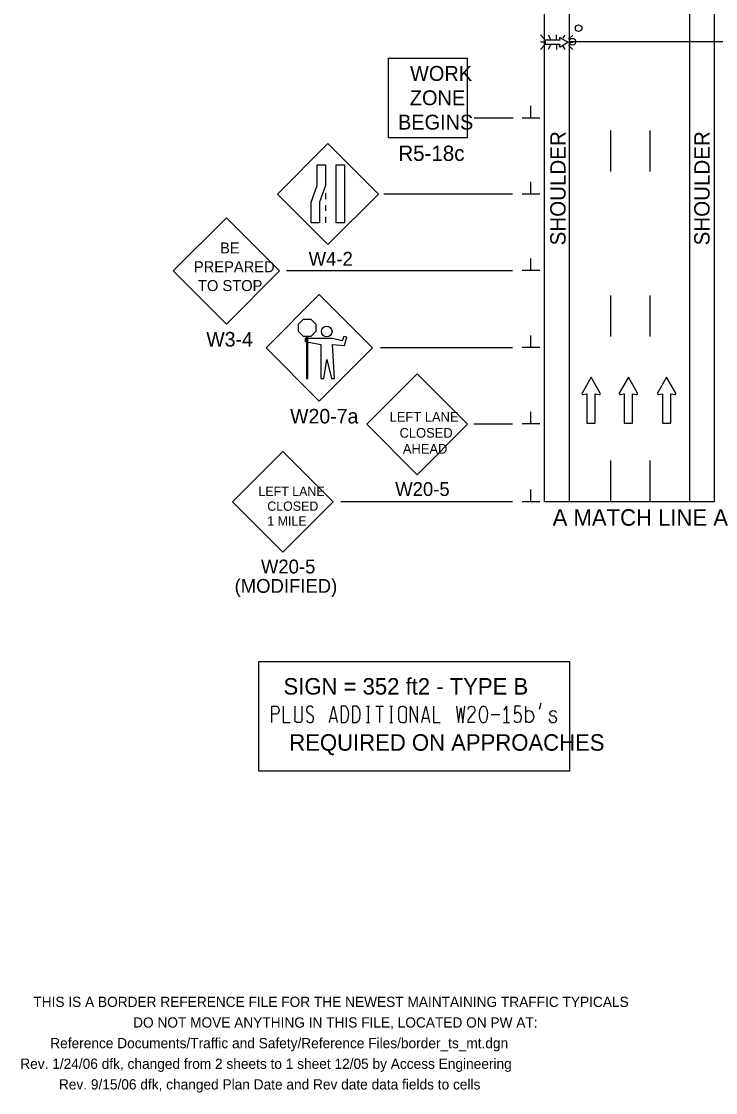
# Model space of a CAD drawing. Extents: x -1809 to 1557, y -1087 to 44.
# Drawn here: x -1809 to -1388, y -1087 to -438 of the extents above; entities that cross this region are included whole.
import ezdxf

# ---------------------------------------------------------------- set-up
doc = ezdxf.new("R2010")
doc.units = 0
for name, color, linetype in [('BORDER', 7, 'Continuous'), ('MT_SCRATCH_LEVEL_A', 7, 'Continuous'), ('MT_SCRATCH_LEVEL_E', 7, 'Continuous'), ('MT_STAGE_1A_NOTES', 7, 'Continuous'), ('PAVT_EDGE_EX', 7, 'Continuous'), ('SCRATCH_LEVEL_A', 7, 'Continuous'), ('SCRATCH_LEVEL_C', 7, 'Continuous'), ('TRAFFIC_SIGNS_PR', 7, 'Continuous'), ('TYPICAL_EX', 7, 'Continuous'), ('TYPICAL_TEXT_DIMEN_EX', 7, 'Continuous')]:
    doc.layers.add(name, color=color, linetype=linetype)

msp = doc.modelspace()

# ---------------------------------------------------------------- linework, layer by layer
at = {"layer": 'BORDER'}
for p, q in [((-1403.94, -403.77), (-1403.94, -728.63)), ((-1451.94, -503.63), (-1451.94, -528.63)), ((-1427.94, -503.63), (-1427.94, -528.63)), ((-1451.94, -603.63), (-1451.94, -628.63)), ((-1427.94, -603.63), (-1427.94, -628.63)), ((-1451.94, -703.63), (-1451.94, -728.63)), ((-1427.94, -703.63), (-1427.94, -728.63))]:
    msp.add_line(p, q, dxfattribs=at)
at = {"layer": 'MT_SCRATCH_LEVEL_A'}
msp.add_line((-1476.89, -407), (-1476.89, -728.63), dxfattribs=at)
at = {"layer": 'MT_SCRATCH_LEVEL_E'}
for p, q in [((-1463.64, -653.15), (-1469.12, -662.8)), ((-1458.11, -662.8), (-1463.64, -653.15)), ((-1441.03, -653.15), (-1446.51, -662.8)), ((-1435.5, -662.8), (-1441.03, -653.15)), ((-1417.86, -653.15), (-1423.34, -662.8)), ((-1412.33, -662.8), (-1417.86, -653.15)), ((-1468.47, -663.71), (-1466.1, -663.29)), ((-1466.1, -663.29), (-1466.1, -680.97)), ((-1461.12, -680.97), (-1461.12, -663.29)), ((-1461.12, -663.29), (-1458.75, -663.71)), ((-1445.87, -663.71), (-1443.5, -663.29)), ((-1443.5, -663.29), (-1443.5, -680.97)), ((-1438.51, -680.97), (-1438.51, -663.29)), ((-1438.51, -663.29), (-1436.14, -663.71)), ((-1422.69, -663.71), (-1420.32, -663.29)), ((-1420.32, -663.29), (-1420.32, -680.97)), ((-1415.34, -680.97), (-1415.34, -663.29)), ((-1415.34, -663.29), (-1412.97, -663.71)), ((-1466.1, -680.97), (-1461.12, -680.97)), ((-1443.5, -680.97), (-1438.51, -680.97)), ((-1420.32, -680.97), (-1415.34, -680.97))]:
    msp.add_line(p, q, dxfattribs=at)
for centre, start, end in [((-1468.57, -663.1), 150.42484, 279.96381), ((-1458.65, -663.1), 260.03619, 29.77312), ((-1445.97, -663.1), 150.42484, 279.96381), ((-1436.05, -663.1), 260.03619, 29.77312), ((-1422.79, -663.1), 150.42484, 279.96381), ((-1412.87, -663.1), 260.03619, 29.77312)]:
    msp.add_arc(centre, 0.617, start, end, dxfattribs=at)
at = {"layer": 'MT_STAGE_1A_NOTES'}
for p, q in [((-1270.82, -449.93), (-1476.89, -449.93)), ((-1510.9, -496.19), (-1534.4, -496.19)), ((-1511.17, -542.25), (-1589.17, -542.25)), ((-1511.17, -588.81), (-1648.17, -588.81)), ((-1511.17, -635.38), (-1591.17, -635.39)), ((-1511.17, -681.74), (-1534.67, -681.74)), ((-1511.17, -728.63), (-1615.18, -728.63))]:
    msp.add_line(p, q, dxfattribs=at)
at = {"layer": 'PAVT_EDGE_EX'}
for p, q in [((-1492.05, -380.59), (-1492.05, -728.63)), ((-1389.15, -407), (-1389.15, -728.63)), ((-1389.15, -728.63), (-1491.84, -728.63))]:
    msp.add_line(p, q, dxfattribs=at)
at = {"layer": 'SCRATCH_LEVEL_C'}
for p, q in [((-1664.91, -825.36), (-1476.63, -825.36)), ((-1664.91, -891.86), (-1664.91, -825.36)), ((-1476.63, -825.36), (-1476.63, -891.86)), ((-1632.6, -852.88), (-1632.02, -853.27)), ((-1476.63, -891.86), (-1664.91, -891.86))]:
    msp.add_line(p, q, dxfattribs=at)
for points in [[(-1657.1, -862.49), (-1657.1, -852.49)], [(-1657.1, -852.49), (-1654.19, -852.49)], [(-1654.19, -852.49), (-1653.31, -852.91), (-1652.69, -854.52), (-1652.69, -855.41), (-1653.31, -857.07), (-1654.19, -857.44)], [(-1650.1, -852.49), (-1650.1, -862.49)], [(-1643.1, -852.49), (-1643.1, -860.41)], [(-1638.73, -860.41), (-1638.73, -852.49)], [(-1635.56, -853.27), (-1636.09, -854.52), (-1636.09, -854.94), (-1635.54, -856.19)], [(-1632.6, -852.88), (-1633.17, -852.49), (-1634.35, -852.49), (-1635.56, -853.27)], [(-1635.54, -856.19), (-1632.29, -858.32)], [(-1622.1, -862.49), (-1619.77, -852.49)], [(-1619.77, -852.49), (-1617.44, -862.49)], [(-1612.48, -852.49), (-1615.1, -852.49)], [(-1615.1, -852.49), (-1615.1, -862.49)], [(-1612.48, -852.49), (-1611.57, -853.27), (-1610.97, -854.94), (-1610.65, -857.15), (-1611, -859.91), (-1611.6, -861.68), (-1612.48, -862.49)], [(-1605.48, -852.49), (-1608.1, -852.49)], [(-1608.1, -852.49), (-1608.1, -862.49)], [(-1605.48, -852.49), (-1604.57, -853.27), (-1603.97, -854.94), (-1603.65, -857.15), (-1604, -859.91), (-1604.6, -861.68), (-1605.48, -862.49)], [(-1599.65, -852.49), (-1597.9, -852.49)], [(-1598.77, -852.49), (-1598.77, -862.49)], [(-1594.1, -852.49), (-1589.44, -852.49)], [(-1591.77, -852.49), (-1591.77, -862.49)], [(-1585.65, -852.49), (-1583.9, -852.49)], [(-1584.77, -852.49), (-1584.77, -862.49)], [(-1580.07, -854.37), (-1579.92, -853.69), (-1579.56, -853.19), (-1578.84, -852.71), (-1578.15, -852.49), (-1577.22, -852.49), (-1576.76, -852.67), (-1575.87, -853.24), (-1575.56, -853.69), (-1575.41, -854.37)], [(-1580.07, -860.62), (-1580.07, -854.37)], [(-1575.41, -860.62), (-1575.41, -854.37)], [(-1573.1, -862.49), (-1573.1, -852.49)], [(-1573.1, -852.49), (-1568.69, -862.49)], [(-1568.69, -862.49), (-1568.69, -852.49)], [(-1566.1, -862.49), (-1563.77, -852.49)], [(-1563.77, -852.49), (-1561.44, -862.49)], [(-1559.1, -852.49), (-1559.1, -862.49)], [(-1545.1, -852.49), (-1543.94, -862.49)], [(-1543.94, -862.49), (-1542.61, -853.49)], [(-1542.61, -853.49), (-1541.31, -862.52)], [(-1541.31, -862.52), (-1540.09, -852.49)], [(-1538.1, -854.57), (-1537.83, -853.64), (-1537.23, -852.88), (-1536.35, -852.49), (-1535.77, -852.49), (-1534.9, -852.88)], [(-1535.66, -857.75), (-1534.29, -856.19)], [(-1534.9, -852.88), (-1534.3, -853.67), (-1534.02, -854.55), (-1534.02, -855.41), (-1534.29, -856.19)], [(-1530.88, -860.5), (-1531.13, -858.39), (-1531.13, -856.7), (-1530.88, -854.58)], [(-1530.88, -854.58), (-1530, -852.95), (-1529.11, -852.55), (-1528.51, -852.55), (-1527.61, -852.97), (-1526.74, -854.61)], [(-1526.74, -854.61), (-1526.46, -856.72), (-1526.48, -858.39), (-1526.74, -860.5)], [(-1514.77, -852.49), (-1516.52, -854.99)], [(-1514.77, -852.49), (-1514.77, -862.49)], [(-1509.81, -852.49), (-1510.1, -857.07)], [(-1510.1, -857.07), (-1508.68, -856.19), (-1507.76, -856.14), (-1506.9, -856.66), (-1506.29, -857.49), (-1506.02, -858.74), (-1506.02, -859.39)], [(-1506.31, -852.49), (-1509.81, -852.49)], [(-1503.07, -862.49), (-1503.07, -852.49)], [(-1503.07, -856.03), (-1502.16, -855.3)], [(-1502.16, -855.3), (-1501.28, -855.15)], [(-1501.28, -855.15), (-1500.52, -855.3)], [(-1500.52, -855.3), (-1499.79, -855.82)], [(-1499.79, -855.82), (-1499.31, -856.24)], [(-1499.31, -856.24), (-1498.88, -856.92)], [(-1494.92, -854.38), (-1493.77, -850.41)], [(-1488.59, -856.81), (-1488.49, -856.24)], [(-1488.49, -856.24), (-1488.12, -855.72)], [(-1488.12, -855.72), (-1487.43, -855.25)], [(-1487.43, -855.25), (-1486.7, -855.15)], [(-1486.7, -855.15), (-1486.08, -855.25)], [(-1486.08, -855.25), (-1485.5, -855.41)], [(-1485.5, -855.41), (-1484.99, -855.88)], [(-1484.99, -855.88), (-1484.58, -856.29)], [(-1654.19, -857.44), (-1657.1, -857.44)], [(-1650.1, -862.49), (-1646.02, -862.49)], [(-1638.73, -860.41), (-1639.02, -861.87), (-1639.6, -862.49), (-1641.94, -862.49), (-1642.83, -861.71), (-1643.1, -860.41)], [(-1636.1, -861.24), (-1635.21, -862.13)], [(-1635.21, -862.13), (-1634.48, -862.45), (-1633.19, -862.44), (-1632.29, -861.71)], [(-1632.29, -861.71), (-1631.7, -860.43), (-1631.71, -859.57), (-1632.29, -858.32)], [(-1618.02, -859.99), (-1621.52, -859.99)], [(-1615.1, -862.49), (-1612.48, -862.49)], [(-1608.1, -862.49), (-1605.48, -862.49)], [(-1599.65, -862.49), (-1597.9, -862.49)], [(-1585.65, -862.49), (-1583.9, -862.49)], [(-1580.07, -860.62), (-1579.92, -861.29), (-1579.56, -861.79), (-1578.84, -862.27), (-1578.15, -862.49), (-1577.22, -862.49), (-1576.76, -862.32), (-1575.87, -861.74), (-1575.56, -861.29), (-1575.41, -860.62)], [(-1562.02, -859.99), (-1565.52, -859.99)], [(-1559.1, -862.49), (-1555.02, -862.49)], [(-1538.1, -861.66), (-1537.83, -860.85)], [(-1538.1, -862.49), (-1538.1, -861.66)], [(-1534.02, -862.49), (-1538.1, -862.49)], [(-1537.83, -860.85), (-1535.66, -857.75)], [(-1526.74, -860.5), (-1527.65, -862.14), (-1528.52, -862.55), (-1529.13, -862.55), (-1530, -862.16), (-1530.88, -860.5)], [(-1524.1, -857.49), (-1518.85, -857.49)], [(-1516.62, -862.49), (-1512.99, -862.49)], [(-1506.02, -859.39), (-1506, -859.99), (-1506.29, -861.24), (-1506.9, -862.1), (-1508.08, -862.49), (-1508.94, -862.4), (-1509.56, -862.1), (-1510.1, -861.27)], [(-1502.38, -862.28), (-1503.07, -861.66)], [(-1501.28, -862.49), (-1502.38, -862.28)], [(-1500.44, -862.33), (-1501.28, -862.49)], [(-1499.86, -861.92), (-1500.44, -862.33)], [(-1499.06, -861.03), (-1499.86, -861.92)], [(-1498.77, -860.51), (-1499.06, -861.03)], [(-1498.88, -856.92), (-1498.62, -857.54)], [(-1498.44, -859.68), (-1498.77, -860.51)], [(-1498.62, -857.54), (-1498.44, -858.12)], [(-1498.44, -858.12), (-1498.4, -858.84)], [(-1498.4, -858.84), (-1498.44, -859.68)], [(-1488.92, -860.15), (-1489.03, -860.51)], [(-1489.03, -860.51), (-1488.92, -861.08)], [(-1488.92, -861.08), (-1488.67, -861.66)], [(-1488.67, -861.66), (-1487.61, -862.44)], [(-1488.41, -857.44), (-1488.59, -856.81)], [(-1488.16, -857.91), (-1488.41, -857.44)], [(-1487.72, -858.27), (-1488.16, -857.91)], [(-1487.14, -858.43), (-1487.72, -858.27)], [(-1487.61, -862.44), (-1486.74, -862.49)], [(-1486.66, -858.48), (-1487.14, -858.43)], [(-1486.74, -862.49), (-1485.97, -862.44)], [(-1485.9, -858.64), (-1486.66, -858.48)], [(-1485.97, -862.44), (-1485.46, -862.18)], [(-1485.31, -858.9), (-1485.9, -858.64)], [(-1485.46, -862.18), (-1485.02, -861.87)], [(-1484.88, -859.31), (-1485.31, -858.9)], [(-1485.02, -861.87), (-1484.58, -861.24)], [(-1484.58, -859.89), (-1484.88, -859.31)], [(-1484.44, -860.46), (-1484.58, -859.89)], [(-1484.58, -861.24), (-1484.44, -860.46)]]:
    msp.add_lwpolyline(points, dxfattribs=at)
at = {"layer": 'TRAFFIC_SIGNS_PR'}
for p, q in [((-1491.77, -448.4), (-1494.31, -445.86)), ((-1489.7, -445.87), (-1488.24, -448.41)), ((-1484.5, -448.41), (-1484.49, -445.87)), ((-1479.57, -445.88), (-1480.66, -447.76)), ((-1474.68, -445.89), (-1477.22, -448.42)), ((-1491.78, -452.06), (-1494.32, -454.6)), ((-1491.77, -450.23), (-1494.31, -450.23)), ((-1488.22, -452.07), (-1489.69, -454.6)), ((-1484.5, -452.07), (-1484.5, -454.61)), ((-1480.74, -452.64), (-1479.6, -454.61)), ((-1477.22, -450.25), (-1474.68, -450.25)), ((-1474.69, -454.62), (-1477.22, -452.08)), ((-1586.43, -507.87), (-1586.43, -459.87)), ((-1586.43, -459.87), (-1538.43, -459.87)), ((-1538.43, -507.87), (-1538.43, -459.87)), ((-1623.04, -511.7), (-1653.58, -542.25)), ((-1592.49, -542.25), (-1623.04, -511.7)), ((-1586.43, -507.87), (-1538.43, -507.87)), ((-1653.58, -542.25), (-1623.04, -572.8)), ((-1624.44, -541.7), (-1624.44, -545.3)), ((-1623.04, -572.8), (-1592.49, -542.25)), ((-1624.44, -548.9), (-1624.44, -552.5)), ((-1684.56, -556.57), (-1716.8, -588.81)), ((-1652.32, -588.81), (-1684.56, -556.57)), ((-1624.44, -556.1), (-1624.44, -559.7)), ((-1716.8, -588.81), (-1684.56, -621.05)), ((-1684.56, -621.05), (-1652.32, -588.81)), ((-1628.31, -603.15), (-1660.56, -635.39)), ((-1596.07, -635.39), (-1628.31, -603.15)), ((-1660.56, -635.39), (-1628.31, -667.63)), ((-1628.31, -667.63), (-1596.07, -635.39)), ((-1568.97, -651.19), (-1599.52, -681.74)), ((-1538.43, -681.74), (-1568.97, -651.19)), ((-1599.52, -681.74), (-1568.97, -712.29)), ((-1568.97, -712.29), (-1538.43, -681.74)), ((-1650.33, -698.13), (-1680.88, -728.67)), ((-1619.79, -728.67), (-1650.33, -698.13)), ((-1680.88, -728.67), (-1650.33, -759.22)), ((-1650.33, -759.22), (-1619.79, -728.67))]:
    msp.add_line(p, q, dxfattribs=at)
for points in [[(-1482.41, -452.96), (-1477.63, -450.25), (-1482.4, -447.51)], [(-1482.85, -447.83), (-1482.65, -448.99), (-1491.4, -448.99), (-1491.4, -451.46), (-1482.65, -451.46), (-1482.86, -452.64)]]:
    msp.add_lwpolyline(points, dxfattribs=at)
for points in [[(-1624.44, -524.54), (-1624.44, -537.12), (-1628.2, -547.12), (-1628.2, -559.7), (-1633.26, -559.7), (-1633.26, -547.12), (-1629.5, -537.12), (-1629.5, -524.54)], [(-1613.04, -524.54), (-1613.04, -559.7), (-1618.09, -559.7), (-1618.09, -524.54)], [(-1637.86, -618.01), (-1633.5, -618.01), (-1630.41, -621.1), (-1630.41, -625.46), (-1633.5, -628.55), (-1637.86, -628.55), (-1640.94, -625.46), (-1640.94, -621.1)], [(-1620.38, -629.78), (-1636.79, -629.78), (-1636.79, -631.57), (-1627.33, -633.29), (-1627.33, -653.95), (-1625.55, -653.95), (-1623.77, -642.55), (-1620.92, -653.95), (-1619.14, -653.95), (-1620.21, -633.29), (-1613.08, -634), (-1611.66, -629.02), (-1613.39, -628.59), (-1614.45, -631.08)], [(-1636.03, -628.55), (-1636.03, -653.93), (-1635.32, -653.93), (-1635.32, -628.55)]]:
    msp.add_lwpolyline(points, close=True, dxfattribs=at)
for centre, radius in [((-1471.15, -441.74), 2), ((-1474.89, -449.93), 2), ((-1623.79, -625.49), 3.21)]:
    msp.add_circle(centre, radius, dxfattribs=at)
for centre, start, end in [((-1482.55, -447.78), 61.42271, 189.89875), ((-1482.55, -452.69), 170.6702, 298.83107)]:
    msp.add_arc(centre, 0.307, start, end, dxfattribs=at)
at = {"layer": 'TYPICAL_EX'}
for p, q in [((-1500.04, -496.18), (-1500.04, -488.79)), ((-1500.04, -496.18), (-1505.38, -496.18)), ((-1494.69, -496.18), (-1500.04, -496.18)), ((-1500.04, -542.25), (-1500.04, -534.85)), ((-1500.04, -542.25), (-1505.38, -542.25)), ((-1494.69, -542.25), (-1500.04, -542.25)), ((-1500.04, -588.64), (-1500.04, -581.24)), ((-1500.04, -588.64), (-1505.38, -588.64)), ((-1494.69, -588.64), (-1500.04, -588.64)), ((-1500.04, -635.29), (-1500.04, -627.89)), ((-1500.04, -635.29), (-1505.38, -635.29)), ((-1494.69, -635.29), (-1500.04, -635.29)), ((-1500.04, -681.52), (-1500.04, -674.12)), ((-1500.04, -681.52), (-1505.38, -681.52)), ((-1494.69, -681.52), (-1500.04, -681.52)), ((-1500.04, -728.71), (-1500.04, -721.32)), ((-1500.04, -728.71), (-1505.38, -728.71)), ((-1494.69, -728.71), (-1500.04, -728.71))]:
    msp.add_line(p, q, dxfattribs=at)

# ---------------------------------------------------------------- texts
at = {"layer": 'SCRATCH_LEVEL_A'}
for s, p in [('THIS IS A BORDER REFERENCE FILE FOR THE NEWEST MAINTAINING TRAFFIC TYPICALS', (-1801.53, -1034.74)), ('DO NOT MOVE ANYTHING IN THIS FILE, LOCATED ON PW AT:', (-1741.09, -1047.24)), ('Reference Documents/Traffic and Safety/Reference Files/border_ts_mt.dgn', (-1791.27, -1059.74)), ('Rev. 1/24/06 dfk, changed from 2 sheets to 1 sheet 12/05 by Access Engineering', (-1809.44, -1072.24)), ('Rev. 9/15/06 dfk, changed Plan Date and Rev date data fields to cells', (-1786.03, -1084.74))]:
    msp.add_text(s, height=6.2, dxfattribs=at).set_placement(p)
at = {"layer": 'SCRATCH_LEVEL_C'}
for s, p in [('SIGN = 352 ft2 - TYPE B', (-1649.98, -845.49)), ('REQUIRED ON APPROACHES', (-1646.47, -879.49))]:
    msp.add_text(s, height=10, dxfattribs=at).set_placement(p)
at = {"layer": 'TRAFFIC_SIGNS_PR'}
for s, height, p in [('WORK', 9.021, (-1573.28, -473.66)), ('ZONE', 9.021, (-1573.43, -488.42)), ('BEGINS', 9.021, (-1580.58, -503.18)), ('R5-18c', 9.3, (-1580.41, -522.17)), ('BE', 6.65, (-1688.38, -578.21)), ('W4-2', 8.37, (-1634.74, -585.66)), ('PREPARED', 6.65, (-1704.26, -589.61)), ('TO STOP', 6.65, (-1701.78, -601.01)), ('W3-4', 8.835, (-1696.76, -634.64)), ('W20-7a', 8.835, (-1645.96, -681.22)), ('LEFT LANE', 5.85, (-1585.67, -680.17)), ('CLOSED', 5.85, (-1579.65, -689.85)), ('AHEAD', 5.85, (-1577.64, -699.52)), ('LEFT LANE', 5.624, (-1665.15, -725.13)), ('W20-5', 8.37, (-1582.28, -725.16)), ('CLOSED', 5.624, (-1659.8, -734.13)), ('1 MILE', 5.624, (-1659.8, -743.12)), ('W20-5', 8.369, (-1663.64, -772.09)), ('(MODIFIED)', 8.369, (-1679.59, -783.83))]:
    msp.add_text(s, height=height, dxfattribs=at).set_placement(p)
at = {"layer": 'TYPICAL_TEXT_DIMEN_EX'}
for p in [(-1479.07, -573.32), (-1391.81, -573.32)]:
    msp.add_text('SHOULDER', height=9.305, rotation=90, dxfattribs=at).set_placement(p)
msp.add_text('A MATCH LINE A', height=10, dxfattribs=at).set_placement((-1486.91, -743.19))

doc.saveas('drawing.dxf')
